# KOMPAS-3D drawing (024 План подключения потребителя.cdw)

Referenced files in D:\Program Files\ASCON\KOMPAS-3D V6 Plus\Templates\: Раб. чертеж зданий и сооружений А1.cdt
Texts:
  ПСПД-0000-2015
  - теплотрасса
  Раб. чертеж зданий и сооружений А1.cdt
  Узел учета тепловой энергии,
  теплоносителя
  Пров.
  Журавлев
  План подключения потребителя
  к тепловой сети
  ЗАО "ПромСервис"
  Разраб.
  ГИП
  Касимов
  Рабоч. чертеж зданий и сооруж. ГОСТ Р 21.1101-2009 Ф3.
  Лит-Масса-Масштаб
  Материал-Предприятие
  Стадия
  Лист
  Листов
  Изм.
  Кол.уч.
  №док.
  Подп.
  Дата
  Изменение
  Номер документа
  Подпись
  Обозначение документа
  Наименование предприятия, в состав которого входит здание (сооружение)
  Наименование здания (сооружения)
  Порядковый номер листа
  Количество листов в документе
  Должность подписавшего
  Наименование изображения
  Индекс предприятия, выпускающего документ
  Инв. № подл.
  Подп. и дата
  Взам. инв. №
  Инвентарный номер подлинника
  Подпись принявшего подлинник на хранение
  Инвентарный номер подлинника, взамен которого выпущен данный подлинник
  Согласовано
  Согласование
  Рабоч. чертеж зданий и сооруж. ГОСТ 21.101-97 Ф3.
Dimensions and other numbers on the sheet: 1:1; 1; 21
